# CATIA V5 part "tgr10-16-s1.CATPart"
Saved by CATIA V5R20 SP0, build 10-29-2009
Part number: TGR10-16-S1
Revision: 1
Definition: design
Nomenclature: TGR10-16-S1
Source: made
Description: NOT SPECIFIED
Bounding box of the stored display mesh (mm): x -22 to 0.8, y 0 to 10, z -5 to 5
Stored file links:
  C:\Users\Raffaele\Desktop\3D X SITO CF\I-MOLD\TGR-S1\tgr10-s1.step\tgr10-16-s1.CATPart
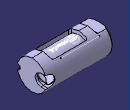
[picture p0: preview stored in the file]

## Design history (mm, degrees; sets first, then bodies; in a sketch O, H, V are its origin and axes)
Set1
  Line1 "LINE #4436": stored without definition
  DatumCurve1 "COMPOSITE_CURVE #4496"
  DatumCurve2 "COMPOSITE_CURVE #4547"
  DatumCurve3 "COMPOSITE_CURVE #4691"
  DatumCurve4 "COMPOSITE_CURVE #4770"
  DatumCurve5 "COMPOSITE_CURVE #4799"
  DatumCurve6 "COMPOSITE_CURVE #4857"
  DatumCurve7 "COMPOSITE_CURVE #4914"
  DatumCurve8 "COMPOSITE_CURVE #4957"
  DatumCurve9 "COMPOSITE_CURVE #5186"
  DatumCurve10 "COMPOSITE_CURVE #5213"
  DatumSurface1 "OPEN_SHELL #4426"
Body1 "MANIFOLD_SOLID_BREP #4427" (main body)
  Solid1: solid without history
